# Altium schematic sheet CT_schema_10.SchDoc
size 281 x 153 mm
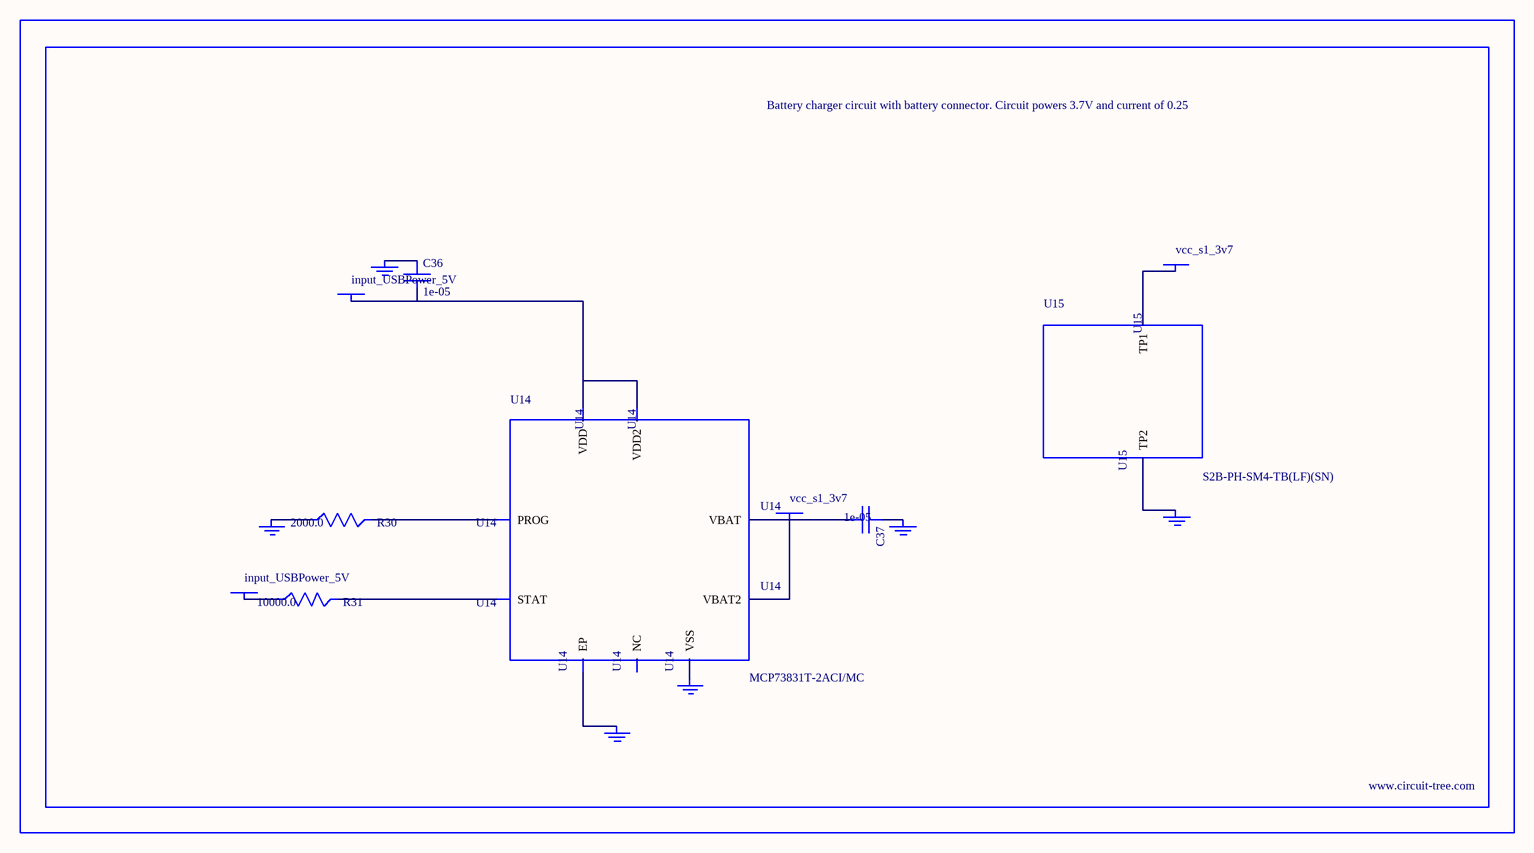
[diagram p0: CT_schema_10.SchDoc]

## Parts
BORDER9  (no value)
C36  1e-05  [C1206]
C37  1e-05  [C1206]
GND_INSTANCE_9_0  (no value)
GND_INSTANCE_9_1  (no value)
GND_INSTANCE_9_2  (no value)
GND_INSTANCE_9_3  (no value)
GND_INSTANCE_9_4  (no value)
GND_INSTANCE_9_5  (no value)
POWER_INSTANCE_9_0  input_USBPower_5V
POWER_INSTANCE_9_1  input_USBPower_5V
POWER_INSTANCE_9_2  vcc_s1_3v7
POWER_INSTANCE_9_3  vcc_s1_3v7
R30  2000.0  [R0603]
R31  10000.0  [R0603]
U14  MCP73831T-2ACI/MC  [DFN8_2X3MC]
U15  S2B-PH-SM4-TB(LF)(SN)  [JST-2-SMD]

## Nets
NetC36_1: C36.1 GND_INSTANCE_9_0.0(GND)
NetC36_2: C36.2 POWER_INSTANCE_9_0.0(PWR) U14.1(VDD) U14.2(VDD2)
NetC37_1: C37.1 GND_INSTANCE_9_1.0(GND)
NetC37_2: C37.2 POWER_INSTANCE_9_2.0(PWR) U14.3(VBAT) U14.4(VBAT2)
NetGND_INSTANCE_9_2_0: GND_INSTANCE_9_2.0(GND) R30.1
NetGND_INSTANCE_9_3_0: GND_INSTANCE_9_3.0(GND) U14.9(EP)
NetGND_INSTANCE_9_4_0: GND_INSTANCE_9_4.0(GND) U14.6(VSS)
NetGND_INSTANCE_9_5_0: GND_INSTANCE_9_5.0(GND) U15.2(TP2)
NetPOWER_INSTANCE_9_1_0: POWER_INSTANCE_9_1.0(PWR) R31.1
NetPOWER_INSTANCE_9_3_0: POWER_INSTANCE_9_3.0(PWR) U15.1(TP1)
NetR30_2: R30.2 U14.8(PROG)
NetR31_2: R31.2 U14.5(STAT)

Not connected (* = marked no-connect by the designer): U14 7(NC)

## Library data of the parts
BORDER9 = BORDER_PAGE9
C36 C37 = C1206C106K3RACTU
GND_INSTANCE_9_0-GND_INSTANCE_9_5 = GND
POWER_INSTANCE_9_0-POWER_INSTANCE_9_3 = PWR
R30 = RC0603JR-072KL
R31 = RC0603JR-0710KL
